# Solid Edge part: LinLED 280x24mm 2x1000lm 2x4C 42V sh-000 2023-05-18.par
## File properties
Author: jaroslaw.przewlocki
Template: iso metric part.par
Last saved by: jaroslaw.przewlocki
Revision: 1
Application: Solid Edge
Gęstość: 0,000 kg/m^3
Dokładność: 0,990
Username: jaroslaw.przewlocki
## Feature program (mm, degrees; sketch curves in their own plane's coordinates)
body "unnamed Body 1"
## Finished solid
Body 1: solid body, 2824 faces, 7208 edges, 4572 vertices.
  Faces by surface: plane 1665, cylinder 535, torus 256, cone 200, spline 104, sphere 64
  Edges by curve: line 4746, curve on surface 1424, circle 630, ellipse 264, spline 144
Bounding box of the edges (mm; curved faces can reach further): 279.600 x 24.000 x 4.450, from (-139.8, -12, 0) to (139.8, 12, 4.45).
Cylindrical faces by radius (mm): R0.2 x184, R0.2169 x24, R0.25 x58, R0.3373 x24, R0.4 x32, R0.4006 x8, R0.4008 x8, R0.525 x8, R0.6 x80, R1 x32, R1.1 x16, R1.1989 x8, R1.199 x8, R1.2 x40, R2.15 x5
Conical faces (half-angle, radius in mm at the cone's reference point): 0.398 deg R1.1964 x8, 0.4493 deg R1.1964 x8, 0.4746 deg R1.1948 x8, 0.4758 deg R1.1948 x8, 0.5 deg R0.5056 x16, 0.5 deg R1.0082 x16, 1 deg R0.5511 x8, 10 deg R0.2132 x16, 10 deg R0.4132 x16, 16.0099 deg R1.1053 x8, 16.1249 deg R1.1279 x8, 18.8604 deg R1.0669 x16, 19.5041 deg R0.5138 x8, 19.8244 deg R0.5099 x8, 27.363 deg R0.6214 x8, 40.6434 deg R0.5161 x8, 43.3309 deg R0.4892 x8, 45 deg R0.575 x8, 45 deg R0.625 x16
Toroidal faces (ring radius, tube radius in mm): R0.0958 r0.3997 x16, R0.1076 r0.4 x8, R0.1101 r0.4001 x8, R0.1217 r0.4 x8, R0.1234 r0.4 x8, R0.1626 r0.228 x8, R0.1634 r0.2287 x8, R0.3287 r0.2001 x8, R0.3684 r0.2151 x8, R0.3703 r0.4 x8, R0.3818 r0.2 x16, R0.4166 r0.3983 x8, R0.5981 r0.197 x8, R0.5982 r0.197 x8, R0.6009 r0.3968 x8, R0.6009 r0.3969 x8, R0.6227 r0.2 x8, R0.6235 r0.2 x8, R0.8 r0.2 x16, R0.8522 r0.3 x8, R0.9002 r0.2 x8, R0.9018 r0.2 x8, R0.9197 r0.223 x8, R0.9365 r0.2 x8, R0.9663 r0.2263 x8, R0.9665 r0.2263 x8, R1.429 r1.2 x8, R1.8741 r0.2175 x8, R1.9007 r0.2 x8
Spherical faces by radius (mm): R0.2 x48, R0.6 x16
Planar faces by outward normal: +x 176, +y 180, +z 265, -x 176, -y 183, -z 33, oblique 652
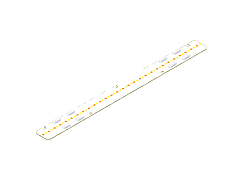
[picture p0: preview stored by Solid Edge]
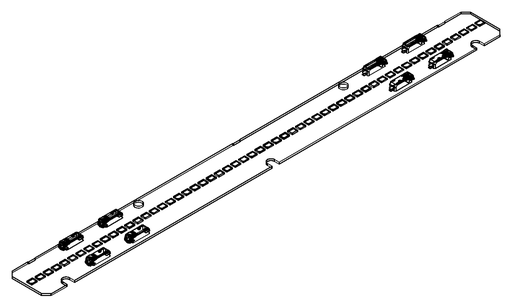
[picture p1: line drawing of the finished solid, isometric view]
